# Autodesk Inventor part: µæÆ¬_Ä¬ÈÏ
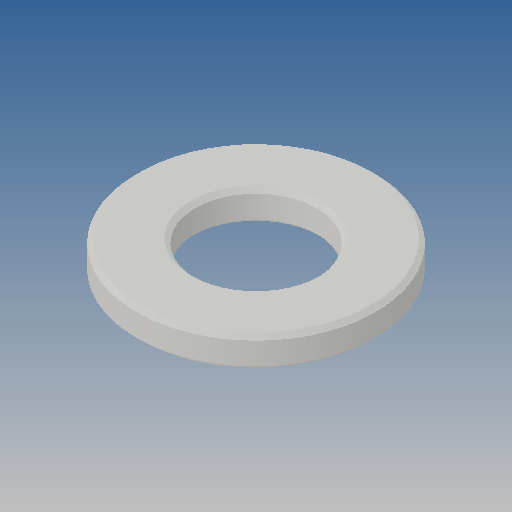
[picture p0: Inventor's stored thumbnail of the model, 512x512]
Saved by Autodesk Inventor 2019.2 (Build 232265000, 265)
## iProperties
Created: 2011-12
Part Number: µæÆ¬_Ä¬ÈÏ
Material: Ogólny
Document SubType Name: Modeling
Designer: CADENGINEERING4
Density: 1 g/cm^3
Appearance: Domyślna
Author: CADENGINEERING4
Revision Number: ÈÎºÎ
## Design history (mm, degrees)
feature "NONE"
node "Bryła1"
